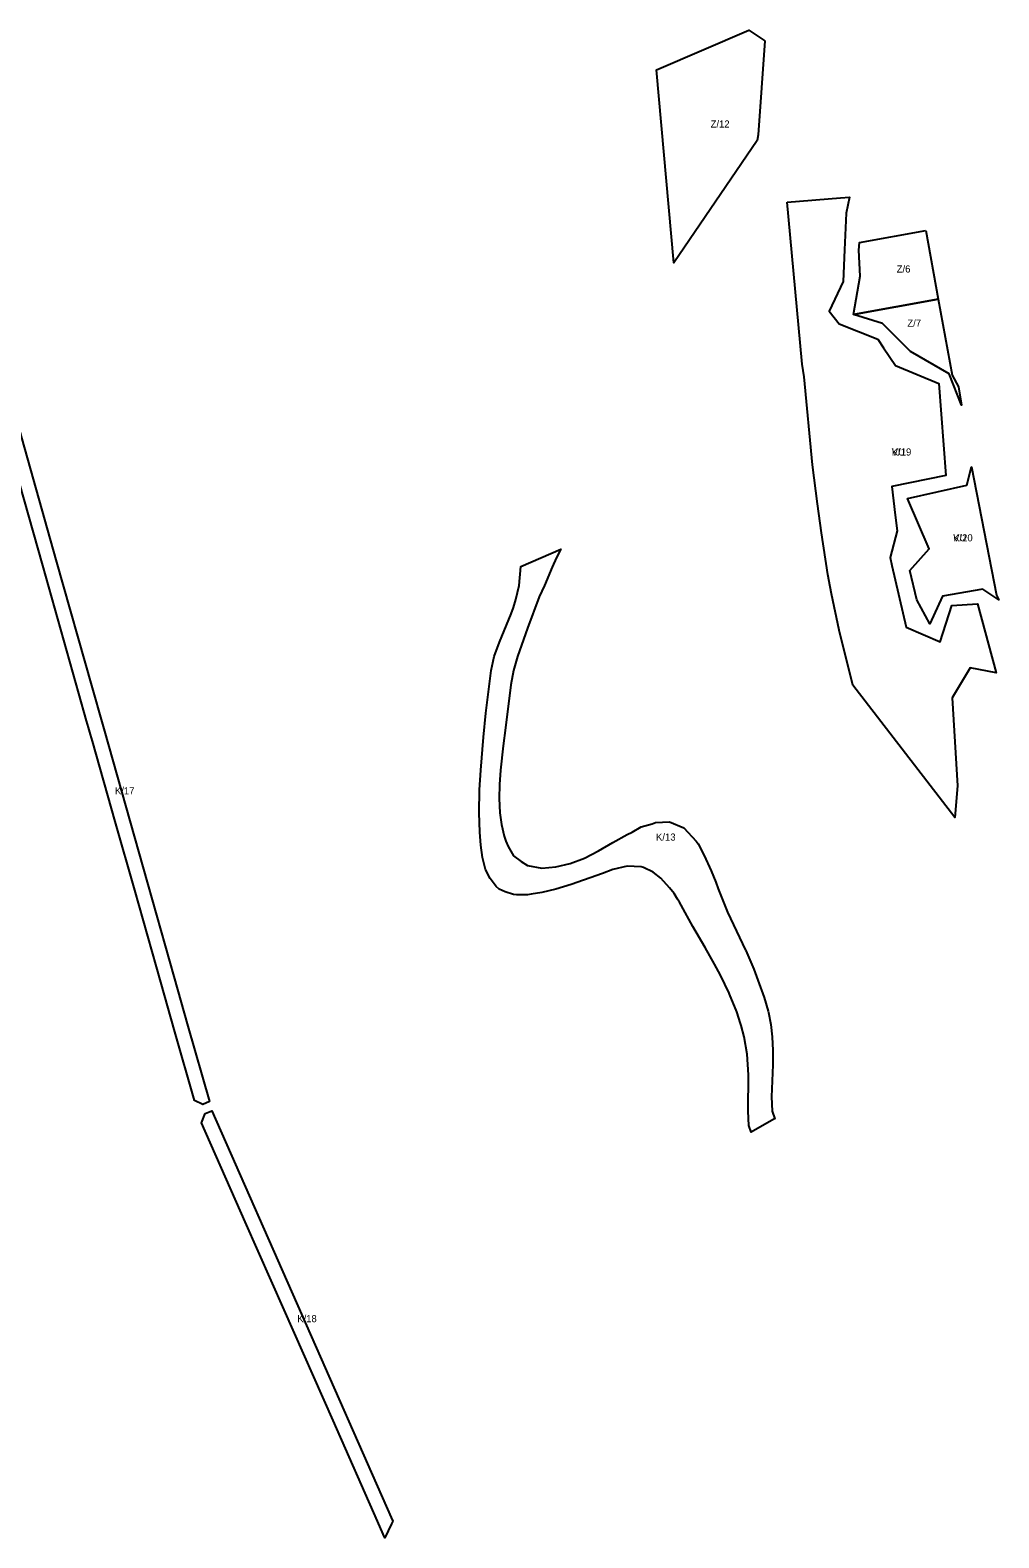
# Model space of a CAD drawing. Extents: x -521969 to -519862, y -1142171 to -1140238.
# Drawn here: x -521119 to -520437, y -1142171 to -1141110 of the extents above; entities that cross this region are included whole.
import ezdxf

# ---------------------------------------------------------------- set-up
doc = ezdxf.new("R2010")
doc.units = 0
for name, color, linetype in [('95420023', 7, 'Continuous'), ('96111023', 7, 'Continuous'), ('96141023', 7, 'Continuous')]:
    doc.layers.add(name, color=color, linetype=linetype)

msp = doc.modelspace()

# ---------------------------------------------------------------- linework, layer by layer
at = {"layer": '95420023'}
for points in [[(-520601.5, -1141117.6), (-520606.1, -1141183.8), (-520607, -1141187.6), (-520665.6, -1141273.9), (-520677.8, -1141138), (-520612.8, -1141110)], [(-520488.3, -1141251.1), (-520479.5, -1141299.4), (-520539.2, -1141310.1), (-520534.4, -1141283.2), (-520535.3, -1141264.9), (-520534.8, -1141259.4)], [(-520479.5, -1141299.4), (-520469.7, -1141352.9), (-520465.2, -1141361), (-520463.1, -1141373.9), (-520471.8, -1141351.9), (-520499.1, -1141336.2), (-520518.6, -1141316.4), (-520539.2, -1141310.1)]]:
    msp.add_lwpolyline(points, close=True, dxfattribs=at)
at = {"layer": '96111023'}
for points in [[(-520585.8, -1141231), (-520548.2, -1141228), (-520541.9, -1141227.5), (-520544.2, -1141238.8), (-520545.4, -1141264.6), (-520546.4, -1141287), (-520556.3, -1141307.7), (-520549.3, -1141316.8), (-520521.9, -1141327.5), (-520517.9, -1141333.5), (-520509.6, -1141346.1), (-520479.1, -1141358.6), (-520474.2, -1141423.4), (-520512.1, -1141431.3), (-520509.7, -1141451.4), (-520508.4, -1141462.4), (-520513.4, -1141481.1), (-520512.1, -1141486.7), (-520502, -1141530.2), (-520478.1, -1141540.6), (-520470, -1141514.9), (-520451.9, -1141513.8), (-520438.6, -1141562.3), (-520457.1, -1141558.7), (-520469.6, -1141579.9), (-520465.9, -1141641.8), (-520467.8, -1141664.2), (-520539.7, -1141570.9), (-520549.2, -1141532.2), (-520554.5, -1141506.8), (-520555.5, -1141501.7), (-520557.2, -1141493.2), (-520561.7, -1141463.9), (-520564.4, -1141443.4), (-520568, -1141415.9), (-520573.9, -1141354), (-520575.3, -1141345.2), (-520582.4, -1141266.6)], [(-520501.1, -1141439.7), (-520459.4, -1141430.3), (-520456.1, -1141417.3), (-520438.5, -1141507.6), (-520436.8, -1141511), (-520448.2, -1141503.5), (-520476.5, -1141508.3), (-520485.3, -1141527.8), (-520494.5, -1141511), (-520499.4, -1141490.3), (-520485.8, -1141475)], [(-520802.6, -1141660.8), (-520802.3, -1141644.6), (-520801.5, -1141630.8), (-520799.4, -1141607.7), (-520797.9, -1141590.8), (-520794.1, -1141560.8), (-520791.9, -1141550.8), (-520788.3, -1141540.8), (-520780.1, -1141520.8), (-520778.5, -1141516.3), (-520776.7, -1141510.8), (-520774.4, -1141500.8), (-520773.3, -1141487.5), (-520745, -1141475.3), (-520748.1, -1141481.1), (-520751.3, -1141487.9), (-520756.6, -1141500.8), (-520760.3, -1141508.9), (-520768.6, -1141530.8), (-520775.5, -1141550.8), (-520778.3, -1141560.8), (-520780.2, -1141570.8), (-520784, -1141601), (-520785.6, -1141613.7), (-520787.5, -1141630.8), (-520788.3, -1141640.8), (-520788.5, -1141650.8), (-520787.9, -1141660.8), (-520786.8, -1141669.1), (-520784.9, -1141677.2), (-520783.8, -1141680.8), (-520782.2, -1141684.5), (-520778.5, -1141691), (-520773, -1141695.2), (-520768.5, -1141697.8), (-520758.5, -1141699.7), (-520748.5, -1141698.9), (-520738.5, -1141696.4), (-520728.5, -1141692.8), (-520718.5, -1141687.6), (-520708.5, -1141681.7), (-520698.5, -1141676.1), (-520694.8, -1141674.5), (-520688.5, -1141670.8), (-520680.7, -1141668.6), (-520678.5, -1141667.7), (-520668.5, -1141667.3), (-520658.5, -1141671.5), (-520649.8, -1141680.8), (-520648.5, -1141682.6), (-520644.1, -1141690.8), (-520639.3, -1141701.6), (-520636.1, -1141709.6), (-520634.3, -1141714.3), (-520627.9, -1141730.8), (-520615.1, -1141757.4), (-520615, -1141757.7), (-520609.2, -1141770.8), (-520606.4, -1141778.7), (-520602, -1141790.8), (-520599.2, -1141800.5), (-520599, -1141801.3), (-520597.4, -1141809.7), (-520596.4, -1141818.6), (-520596, -1141828.2), (-520596, -1141838.3), (-520596.9, -1141860.8), (-520596.3, -1141870.8), (-520594.5, -1141876.2), (-520595.2, -1141876.5), (-520611.2, -1141885.6), (-520612.7, -1141880.8), (-520613.2, -1141870.8), (-520613.1, -1141845.3), (-520614, -1141830.8), (-520616.1, -1141818.4), (-520618.2, -1141810.4), (-520618.6, -1141809.1), (-520621.3, -1141800.8), (-520626.3, -1141788.5), (-520626.7, -1141787.7), (-520632.8, -1141775.1), (-520637, -1141767.4), (-520643.4, -1141755.7), (-520652.2, -1141740.8), (-520660.4, -1141725.8), (-520661.5, -1141723.8), (-520663, -1141721.5), (-520665.4, -1141717.7), (-520668.5, -1141713.6), (-520674.6, -1141706.9), (-520680.2, -1141702.5), (-520687, -1141699.3), (-520688.5, -1141698.8), (-520698.5, -1141698.3), (-520708.5, -1141700.7), (-520715.7, -1141703.6), (-520737.8, -1141711.4), (-520748.5, -1141714.6), (-520758.5, -1141717), (-520765.9, -1141718.2), (-520768.5, -1141718.5), (-520776.2, -1141718.5), (-520778.5, -1141718.3), (-520784.2, -1141716.5), (-520788.5, -1141714.5), (-520790.5, -1141712.8), (-520794.9, -1141707.1), (-520798.1, -1141700.8), (-520800.2, -1141692.4), (-520801.4, -1141683.7), (-520802.1, -1141674.4)], [(-520995.4, -1141872.5), (-520990.8, -1141870.5), (-520864.4, -1142156.7), (-520863.2, -1142159.4), (-520864.2, -1142161.3), (-520868.9, -1142171.1), (-520870.1, -1142168.4), (-520874.2, -1142159.3), (-520905.4, -1142088.6), (-520939.9, -1142010.6), (-520967.3, -1141948.6), (-520997.9, -1141879.1)]]:
    msp.add_lwpolyline(points, close=True, dxfattribs=at)
msp.add_lwpolyline([(-521140.7, -1141340.9), (-521100.5, -1141482.8), (-521075, -1141572.8), (-521068.2, -1141596.8), (-521066.8, -1141601.7), (-521035.7, -1141711.2), (-521017.4, -1141776.1), (-521007.5, -1141810.9), (-520992.4, -1141864.1), (-520997.1, -1141866.1), (-521003, -1141863.4), (-521016.8, -1141814.9), (-521026.6, -1141780.1), (-521045, -1141715.3), (-521058.7, -1141667), (-521074.7, -1141610.5), (-521076, -1141605.7), (-521077.4, -1141600.8), (-521078.8, -1141596.1), (-521084.2, -1141576.9), (-521109.7, -1141486.9), (-521149.2, -1141347.4)], dxfattribs=at)
at = {"layer": '96141023'}
for points in [[(-520585.8, -1141231), (-520548.2, -1141228), (-520541.9, -1141227.5), (-520544.2, -1141238.8), (-520545.4, -1141264.6), (-520546.4, -1141287), (-520556.3, -1141307.7), (-520549.3, -1141316.8), (-520521.9, -1141327.5), (-520517.9, -1141333.5), (-520509.6, -1141346.1), (-520479.1, -1141358.6), (-520474.2, -1141423.4), (-520512.1, -1141431.3), (-520509.7, -1141451.4), (-520508.4, -1141462.4), (-520513.4, -1141481.1), (-520512.1, -1141486.7), (-520502, -1141530.2), (-520478.1, -1141540.6), (-520470, -1141514.9), (-520451.9, -1141513.8), (-520438.6, -1141562.3), (-520457.1, -1141558.7), (-520469.6, -1141579.9), (-520465.9, -1141641.8), (-520467.8, -1141664.2), (-520539.7, -1141570.9), (-520549.2, -1141532.2), (-520554.5, -1141506.8), (-520555.5, -1141501.7), (-520557.2, -1141493.2), (-520561.7, -1141463.9), (-520564.4, -1141443.4), (-520568, -1141415.9), (-520573.9, -1141354), (-520575.3, -1141345.2), (-520582.4, -1141266.6)], [(-520459.4, -1141430.3), (-520456.1, -1141417.3), (-520438.5, -1141507.6), (-520436.8, -1141511), (-520448.2, -1141503.5), (-520476.5, -1141508.3), (-520485.3, -1141527.8), (-520494.5, -1141511), (-520499.4, -1141490.3), (-520485.8, -1141475), (-520501.1, -1141439.7)]]:
    msp.add_lwpolyline(points, close=True, dxfattribs=at)

# ---------------------------------------------------------------- texts
at = {"layer": '95420023'}
for s, rotation, p in [('Z/12', 360, (-520639.7, -1141178.6)), ('Z/6', 0, (-520508.7, -1141280.6)), ('Z/7', 360, (-520501.2, -1141318.7))]:
    msp.add_text(s, height=5, rotation=rotation, dxfattribs=at).set_placement(p)
at = {"layer": '96111023'}
for s, rotation, p in [('K/19', 360, (-520512.2, -1141409.4)), ('K/20', 360, (-520469, -1141469.8)), ('K/17', 0, (-521058.9, -1141647.8)), ('K/13', 0, (-520678.1, -1141680.4)), ('K/18', 0, (-520930.6, -1142019.3))]:
    msp.add_text(s, height=5, rotation=rotation, dxfattribs=at).set_placement(p)
at = {"layer": '96141023'}
for p in [(-520512.2, -1141409.4), (-520469, -1141469.8)]:
    msp.add_text('VU', height=5, rotation=360, dxfattribs=at).set_placement(p)

doc.saveas('drawing.dxf')
